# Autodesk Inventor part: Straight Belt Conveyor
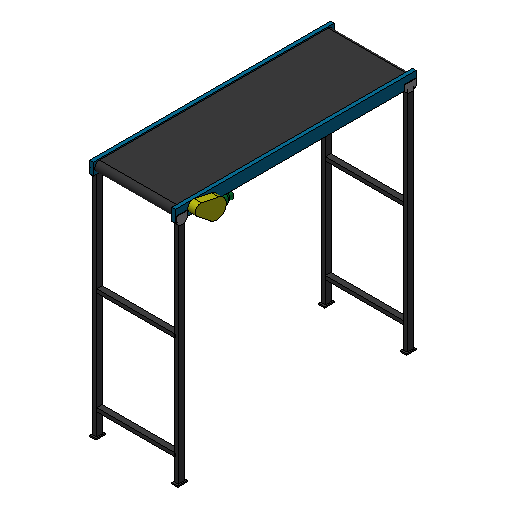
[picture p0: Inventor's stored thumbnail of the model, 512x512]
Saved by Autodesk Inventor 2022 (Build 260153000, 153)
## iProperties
ConnectorClass: Conveyor
family_type: normal
Created: 2009-10
Part Number: Straight Belt Conveyor
Document SubType Name: Modeling
Density: 1 g/cm^3
Material: 一般
Appearance: 既定
Key Parameters: Height=2000.000 mm;Width=710.000 mm;Length=2000.000 mm;RollerDiameter=80.000 mm;NumberOfRungs=2.000 ul;FeetGap=1000.000 mm;MotorLocation="Front-Right";Legs="All
Title: Straight Belt Conveyor
Author: Autodesk, Inc.
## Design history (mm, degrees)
sketch "Sketch1"
  geometry: L1 (1900, 1000)-(1900, -1000); L2 (1900, -1000)-(2000, -1000); L3 (2000, -1000)-(2000, 1000); L4 (2000, 1000)-(1900, 1000); L5 (1950, 1000)-(0, 1000); L6 (1950, -1000)-(0, -1000); L7 (0, -1000)-(0, 1000); L8 (0, -1400)-(0, 1400) reference; 2 further points
  constraints: 14 end point, 3 midpoint, 3 perpendicular, 2 coincident, 2 parallel, 1 collinear
  dimensions: "d110" = 100 distance between parallel lines of L1 L3 (= RailHeight); "d292" = 2000 distance of L6.end L5.end (derived); "d408" = 2000 distance from line of L8 L3.end (derived); "d409" = 2000 distance from line of L7 L2.end (derived)
extrude "Rail1" new body sketch "Sketch1" distance "d112" = 30 (= RailThickness); taper "d113" = 0 deg
node "MID"
mirror "Rail2"
sketch "Sketch8"
  geometry: L1 (-0.5, -25)-(-29.5, -25); L2 (-29.5, -25)-(-29.5, -75); L3 (-29.5, -75)-(-0.5, -75); L4 (-0.5, -75)-(-0.5, -25); L5 (-680, 0)-(-710, 0); L6 (-680.5, -25)-(-709.5, -25); L7 (-709.5, -25)-(-709.5, -75); L8 (-709.5, -75)-(-680.5, -75); L9 (-680.5, -75)-(-680.5, -25); L10 (-30, 0)-(0, 0); 4 further points
  constraints: 20 end point, 4 midpoint, 4 parallel, 3 perpendicular, 2 equal length, 2 horizontal, 2 vertical alignment
  dimensions: "d805" = 29 distance between parallel lines of L2 L4 (derived); "d806" = 50 distance between parallel lines of L3 L1; "d809" = 29 distance between parallel lines of L7 L9; "d810" = 50 distance between parallel lines of L6 L8 (derived); "d811" = 25 distance between parallel lines of L6 L5; "d812" = 25 distance between parallel lines of L1 L10 (derived)
extrude "Leg Mid 1" join sketch "Sketch8" distance "d731" = 1900 (derived); taper "d732" = 0 deg
sketch "Sketch9"
  geometry: L1 (2.5, -1680)-(47.5, -1680); L2 (47.5, -1680)-(47.5, -1710); L3 (47.5, -1710)-(2.5, -1710); L4 (2.5, -1710)-(2.5, -1680); L5 (50, -1900)-(0, -1900) reference; 2 further points
  constraints: 8 end point, 2 midpoint, 2 parallel, 1 horizontal, 1 perpendicular, 1 vertical alignment
  dimensions: "d1060" = 30 distance of L3.end L1.start; "d1071" = 190 distance between parallel lines of L3 L5 (derived); "d1072" = 45 distance of L1.start L1.end
extrude "Rung Mid 1" join sketch "Sketch9" stored distance "d739" = 650 (derived); taper "d740" = 0 deg
node "ToCutBelow"
sketch "ToBeenCutOne"
  geometry: L1 (-30, 1000)-(-680, 1000); L2 (-355, 1000)-(-355, 400); L3 (-30, -1000)-(-680, -1000); L4 (-355, -1000)-(-355, 400); L5 (-284, 400)-(-426, 400); C1 r 35.5 at (-284, 400); C2 r 35.5 at (-426, 400); 1 further point
  constraints: 10 end point, 4 coincident, 4 perpendicular, 3 midpoint, 2 centre point, 1 horizontal
  dimensions: "d720" = 600 distance of L2.start L2.end (derived); "d756" = 142 distance of L5.start L5.end (derived); "d813" = 71 diameter of C1 (derived); "d814" = 71 diameter of C2 (derived)
extrude "ToBeenCutMid" join sketch "ToBeenCutOne" distance "d817" = 25 (derived); taper "d818" = 0 deg
sketch "Sketch10"
  geometry: L1 (-680, 100)-(-30, 100); L2 (-30, 100)-(-30, 0); L3 (-30, 0)-(-680, 0); L4 (-680, 0)-(-680, 100)
  constraints: 8 end point, 2 parallel, 1 horizontal, 1 perpendicular
extrude "Cut Mid" cut sketch "Sketch10" distance "d744" = 2000 (derived); taper "d745" = 0 deg
pattern_linear "Rung Mid 2" dims "d743" = 855 (derived)
sketch "Sketch11"
  geometry: L1 (-0.5, -25)-(-0.5, -75) reference; L2 (-29.5, -25)-(-0.5, -25) reference; L3 (-29.5, -75)-(-29.5, -25) reference; L4 (-0.5, -75)-(-29.5, -75) reference; L5 (-680.5, -25)-(-680.5, -75) reference; L6 (-709.5, -25)-(-680.5, -25) reference; L7 (-709.5, -75)-(-709.5, -25) reference; L8 (-680.5, -75)-(-709.5, -75) reference; L9 (10, -10)-(-40, -10); L10 (-40, -10)-(-40, -90); L11 (-40, -90)-(10, -90); L12 (10, -90)-(10, -10); L13 (-670, -10)-(-720, -10); L14 (-720, -10)-(-720, -90); L15 (-720, -90)-(-670, -90); L16 (-670, -90)-(-670, -10); 9 further points
  constraints: 16 end point, 8 midpoint, 4 parallel, 2 horizontal, 2 horizontal alignment, 2 perpendicular, 2 vertical alignment
  dimensions: "d1001" = 80 distance of L11.end L9.start; "d1002" = 50 distance of L10.end L11.end; "d1003" = 80 distance of L15.end L13.start; "d1004" = 50 distance of L14.end L15.end
extrude "LegBase" join sketch "Sketch11" distance "d1005" = 10.2 (derived); taper "d1006" = 0 deg
sketch "Sketch12"
  geometry: L1 (50, 0)-(0, 0) reference; L2 (-24, 47.55)-(74, 47.55); L3 (74, 47.55)-(74, -2.45); L4 (74, -2.45)-(45, -30); L5 (45, -30)-(5, -30); L6 (5, -30)-(-24, -2.45); L7 (-24, -2.45)-(-24, 47.55); L8 (0, -1889.8)-(50, -1889.8) reference; L9 (0, 0)-(50, 0) reference; 7 further points
  constraints: 12 end point, 5 midpoint, 4 vertical alignment, 3 equal length, 2 parallel, 2 perpendicular
  dimensions: "d1007" = 40 distance of L4.end L5.end; "d1008" = 98 distance of L2.start L2.end; "d1009" = 30 distance between parallel lines of L1 L5; "d1011" = 50 distance of L6.end L2.start
extrude "LegPan" join sketch "Sketch12" distance "d1012" = 5.1 (derived); taper "d1013" = 0 deg
mirror "LegPanE"
pattern_linear "Leg Mid 2"
pattern_linear "Leg Mid 3" dims "d1075" = 1900 (derived)
mirror "LegMid3"
mirror "LegMid4"
sketch "Sketch20"
  geometry: L1 (-950, 1990)-(950, 1990); L2 (-950, 1910)-(950, 1910); L3 (950, 1990)-(950, 1910); L4 (-950, 1910)-(-950, 1990); L5 (-950, 1950)-(-950, 1950); L6 (-1000, 1900)-(-1000, 2000) reference; L7 (1000, 2000)-(1000, 1900) reference; L8 (-950, 1950)-(-1000, 1950); L9 (950, 1950)-(1000, 1950); L10 (-1000, 2000)-(-1000, 1900) reference; L11 (1000, 1900)-(1000, 2000) reference; C1 r 40 at (-950, 1950); A1 r 40 centre (950, 1950) between (950, 1990) and (950, 1910)
  constraints: 14 end point, 4 midpoint, 4 tangent, 2 centre point, 2 equal length, 2 horizontal alignment, 2 point on circle
  dimensions: "d820" = 80 diameter of A1 (derived); "d831" = 80 diameter of C1 (derived); "d1000" = 0 distance of L5.start L5.end; "d1014" = 50 distance of L5.start L8.end (derived); "d1015" = 50 distance of L9.start L9.end (derived)
extrude "BeltMid" join sketch "Sketch20" distance "d821" = 650 (derived); taper "d822" = 0 deg
sketch "Sketch29"
  geometry: L1 (-1000, 1900)-(-1000, 2000) reference; L2 (1000, 2000)-(1000, 1900) reference; L3 (1000, 1900)-(-1000, 1900) reference; L4 (-1000, 2000)-(1000, 2000) reference; L5 (0, 2000)-(0, 1899); L6 (-75, 1899)-(75, 1899); L7 (-75, 1999)-(75, 1999); L8 (-75, 1799)-(75, 1799); A1 r 100 centre (-75, 1899) between (-75, 1999) and (-75, 1799); A2 r 100 centre (75, 1899) between (75, 1799) and (75, 1999)
  constraints: 8 end point, 4 point on circle, 4 tangent, 2 centre point, 2 coincident, 2 midpoint, 2 parallel, 1 perpendicular
  dimensions: "d1067" = 101 distance of L5.start L5.end; "d1068" = 150 distance of L6.start L6.end; "d1069" = 100 radius of A1
extrude "M2.1" join sketch "Sketch29" distance "d898" = 50; taper "d899" = 0 deg
sketch "Sketch30"
  geometry: L1 (-174.995, 660)-(174.995, 660); L2 (0, 650)-(80, 650); L3 (80, 650)-(80, 550); L4 (80, 550)-(0, 550); L5 (0, 550)-(0, 650); 2 further points
  constraints: 10 end point, 2 midpoint, 2 perpendicular, 1 horizontal, 1 parallel, 1 vertical alignment
  dimensions: "d900" = 100 distance of L4.end L2.start; "d901" = 80 distance of L3.end L4.end; "d1070" = 10 distance between parallel lines of L1 L2
extrude "M2.2" join sketch "Sketch30" distance "d902" = 100; taper "d903" = 0 deg
sketch "Sketch31"
  geometry: L1 (-100, 100)-(-100, 0) reference; L2 (0, 0)-(-100, 0) reference; L3 (0, 100)-(0, 9.125) reference; C1 r 50 at (-50, 50); 2 further points
  constraints: 3 tangent, 1 centre point
extrude "M2.3" join sketch "Sketch31" distance "d904" = 80; taper "d905" = 0 deg
sketch "Sketch32" dims "d907" = 100 (derived)
  geometry: C1 r 15 at (0, 0); 3 further points
  constraints: 1 centre point, 1 coincident, 1 horizontal alignment
  dimensions: "d906" = 30 diameter of C1
extrude "M2.4" join sketch "Sketch32" distance "d908" = 20; taper "d909" = 0 deg
sketch "Sketch33"
  geometry: C1 r 15 at (0, 0) reference; C2 r 40 at (0, 0); 1 further point
  constraints: 1 centre point, 1 coincident
  dimensions: "d910" = 80 diameter of C2
extrude "M2.5" join sketch "Sketch33" distance "d911" = 30; taper "d912" = 0 deg
sketch "Sketch34"
  geometry: L1 (1000, 2000)-(1000, 1900); L2 (1000, 2000)-(1000, 1900) reference; L3 (843.023, 1999.096)-(700.095, 1969.999); L4 (765.848, 1828.993)-(880.009, 1919.779); L5 (-1000, 1900)-(1000, 1900) reference; L6 (852, 1955)-(716.054, 1891.607); L7 (-1000, 2000)-(1000, 2000) reference; A1 r 45 centre (852, 1955) between (880.009, 1919.779) and (843.023, 1999.096); A2 r 80 centre (716.054, 1891.607) between (700.095, 1969.999) and (765.848, 1828.993)
  constraints: 8 end point, 5 tangent, 4 point on circle, 2 centre point, 1 vertical
  dimensions: "d913" = 90 diameter of A1; "d1078" = 150 distance of L6.start L6.end; "d1079" = 148 distance from line of L1 L6.start; "d1080" = 80 radius of A2; "d1081" = 25 deg angle of L5 L6
extrude "M1.1" join sketch "Sketch34" distance "d915" = 50; taper "d916" = 0 deg
sketch "Sketch35"
  geometry: L1 (-716.054, 651.607)-(-636.054, 651.607); L2 (-636.054, 651.607)-(-636.054, 551.607); L3 (-636.054, 551.607)-(-716.054, 551.607); L4 (-716.054, 551.607)-(-716.054, 651.607); A1 r 80 centre (-716.054, 651.607) between (-636.495, 660) and (-765.848, 588.993) reference; 1 further point
  constraints: 8 end point, 2 parallel, 1 horizontal, 1 perpendicular
  dimensions: "d917" = 100 distance of L3.end L1.start; "d1077" = 80 distance of L2.end L3.end
extrude "M1.2" join sketch "Sketch35" distance "d918" = 98; taper "d919" = 0 deg
sketch "Sketch36"
  geometry: L1 (-98, 100)-(-98, 0) reference; L2 (0, 0)-(-98, 0) reference; L3 (0, 0)-(0, 100) reference; C1 r 49 at (-49, 49); 1 further point
  constraints: 3 tangent, 1 centre point
extrude "M1.3" join sketch "Sketch36" distance "d920" = 80; taper "d921" = 0 deg
sketch "Sketch37"
  geometry: C1 r 49 at (0, 0) reference; C2 r 15 at (0, 0); 1 further point
  constraints: 1 centre point, 1 coincident
  dimensions: "d922" = 98 diameter of C1 (derived); "d923" = 30 diameter of C2
extrude "M1.4" join sketch "Sketch37" distance "d924" = 20; taper "d925" = 0 deg
sketch "Sketch38"
  geometry: C1 r 15 at (0, 0) reference; C2 r 40 at (0, 0); 1 further point
  constraints: 1 centre point, 1 coincident
  dimensions: "d926" = 80 diameter of C2
extrude "M1.5" join sketch "Sketch38" distance "d927" = 30; taper "d928" = 0 deg
sketch "Sketch39"
  geometry: L1 (-1000, 1900)-(-1000, 2000) reference; L2 (-843.023, 1999.096)-(-700.095, 1969.999); L3 (-880.009, 1919.779)-(-765.848, 1828.993); L4 (1000, 2000)-(-1000, 2000) reference; L5 (-1000, 1900)-(1000, 1900) reference; L6 (-852, 1955)-(-716.054, 1891.607); L7 (901, 1900)-(999, 1900) reference; A1 r 45 centre (-852, 1955) between (-843.023, 1999.096) and (-880.009, 1919.779); A2 r 80 centre (-716.054, 1891.607) between (-765.848, 1828.993) and (-700.095, 1969.999); A3 r 45 centre (-852, 1955) between (-843.023, 1999.096) and (-880.009, 1919.779); 1 further point
  constraints: 6 end point, 6 point on circle, 4 tangent, 3 centre point, 1 coincident, 1 concentric
  dimensions: "d929" = 90 diameter of A1; "d932" = 160 diameter of A2; "d1082" = 148 distance from line of A1.centre L1; "d1083" = 150 distance of L6.start L6.end; "d1084" = 25 deg angle of L5 L6; "d1111" = 55 distance from line of L7 A1.centre
extrude "M3.1" join sketch "Sketch39" distance "d933" = 60 (derived); taper "d934" = 0 deg
sketch "Sketch40"
  geometry: L1 (716.054, 653.607)-(636.054, 653.607); L2 (636.054, 653.607)-(636.054, 553.607); L3 (636.054, 553.607)-(716.054, 553.607); L4 (716.054, 553.607)-(716.054, 653.607); 4 further points
  constraints: 8 end point, 2 parallel, 1 coincident, 1 horizontal, 1 perpendicular, 1 other
  dimensions: "d935" = 80 distance of L2.end L3.end; "d1085" = 100 distance of L1.end L2.end
extrude "M3.2" join sketch "Sketch40" distance "d936" = 98; taper "d937" = 0 deg
sketch "Sketch41"
  geometry: L1 (98, 0)-(98, 100) reference; L2 (0, 100)-(0, 0) reference; L3 (0, 0)-(98, 0) reference; C1 r 49 at (49, 49); 4 further points
  constraints: 3 tangent, 1 centre point
extrude "M3.3" join sketch "Sketch41" distance "d938" = 80; taper "d939" = 0 deg
sketch "Sketch42"
  geometry: C1 r 49 at (0, 0) reference; C2 r 15 at (0, 0); 1 further point
  constraints: 1 centre point, 1 coincident
  dimensions: "d940" = 30 diameter of C2; "d941" = 98 diameter of C1 (derived)
extrude "M3.4" join sketch "Sketch42" distance "d942" = 20; taper "d943" = 0 deg
sketch "Sketch43"
  geometry: C1 r 15 at (0, 0) reference; C2 r 40 at (0, 0); 1 further point
  constraints: 1 centre point, 1 coincident
  dimensions: "d944" = 80 diameter of C2
extrude "M3.5" join sketch "Sketch43" distance "d945" = 30; taper "d946" = 0 deg
sketch "Sketch44"
  geometry: L1 (-2000, 100)-(-2000, 0) reference; L2 (-1843.023, 99.096)-(-1700.095, 69.999); L3 (-1765.848, -71.007)-(-1880.009, 19.779); L4 (-1852, 55)-(-1716.054, -8.393); L5 (0, 0)-(-2000, 0) reference; L6 (-2000, 100)-(0, 100) reference; A1 r 45 centre (-1852, 55) between (-1843.023, 99.096) and (-1880.009, 19.779); A2 r 80 centre (-1716.054, -8.393) between (-1765.848, -71.007) and (-1700.095, 69.999); A3 r 45 centre (-1852, 55) between (-1843.023, 99.096) and (-1880.009, 19.779)
  constraints: 6 end point, 6 point on circle, 5 tangent, 3 centre point, 1 coincident
  dimensions: "d948" = 90 diameter of A1; "d949" = 160 diameter of A2; "d1086" = 150 distance of L4.start L4.end; "d1087" = 25 deg angle of L4 L5; "d1088" = 148 distance from line of A1.centre L1
extrude "M4.1" join sketch "Sketch44" distance "d950" = 60 (derived); taper "d951" = 0 deg
sketch "Sketch45"
  geometry: L1 (1716.054, -8.393)-(1636.054, -8.393); L2 (1636.054, -8.393)-(1636.054, -108.393); L3 (1636.054, -108.393)-(1716.054, -108.393); L4 (1716.054, -108.393)-(1716.054, -8.393); A1 r 80 centre (1716.054, -8.393) between (1636.495, 0) and (1765.848, -71.007) reference
  constraints: 8 end point, 2 parallel, 1 coincident, 1 horizontal, 1 perpendicular
  dimensions: "d952" = 100 distance of L3.end L1.start; "d1089" = 80 distance of L2.end L3.end
extrude "M4.2" join sketch "Sketch45" distance "d953" = 100; taper "d954" = 0 deg
sketch "Sketch46"
  geometry: L1 (100, 0)-(100, 100) reference; L2 (0, 100)-(0, 0) reference; L3 (0, 0)-(100, 0) reference; C1 r 50 at (50, 50); 3 further points
  constraints: 3 tangent, 1 centre point
extrude "M4.3" join sketch "Sketch46" distance "d955" = 80; taper "d956" = 0 deg
sketch "Sketch47"
  geometry: C1 r 50 at (0, 0) reference; C2 r 15 at (0, 0); 1 further point
  constraints: 1 centre point, 1 coincident
  dimensions: "d957" = 100 diameter of C1 (derived); "d958" = 30 diameter of C2
extrude "M4.4" join sketch "Sketch47" distance "d959" = 20; taper "d960" = 0 deg
sketch "Sketch48"
  geometry: C1 r 15 at (0, 0) reference; C2 r 40 at (0, 0); 1 further point
  constraints: 1 centre point, 1 coincident
  dimensions: "d961" = 80 diameter of C2
extrude "M4.5" join sketch "Sketch48" distance "d962" = 30; taper "d963" = 0 deg
sketch "Sketch49"
  geometry: L1 (-1075, 99)-(-925, 99); L2 (-925, -101)-(-1075, -101); L3 (-2000, 100)-(0, 100) reference; L4 (-1000, 100)-(-1000, -1); L5 (-1075, -1)-(-925, -1); A1 r 100 centre (-1075, -1) between (-1075, 99) and (-1075, -101); A2 r 100 centre (-925, -1) between (-925, -101) and (-925, 99)
  constraints: 8 end point, 4 point on circle, 4 tangent, 2 centre point, 2 coincident, 2 midpoint, 2 perpendicular, 1 equal radius, 1 parallel
  dimensions: "d964" = 200 diameter of A1; "d1090" = 101 distance of L4.start L4.end; "d1091" = 150 distance of L5.start L5.end
extrude "M5.1" join sketch "Sketch49" distance "d965" = 50; taper "d966" = 0 deg
sketch "Sketch50"
  geometry: L1 (920, -10)-(1000, -10); L2 (1000, -10)-(1000, -110); L3 (1000, -110)-(920, -110); L4 (920, -110)-(920, -10); L5 (1174.995, 0)-(825.005, 0) reference; 2 further points
  constraints: 8 end point, 2 midpoint, 2 parallel, 1 horizontal, 1 perpendicular, 1 vertical alignment
  dimensions: "d967" = 100 distance of L3.end L1.start; "d968" = 80 distance between parallel lines of L2 L4; "d1092" = 10 distance between parallel lines of L1 L5
extrude "M5.2" join sketch "Sketch50" distance "d969" = 98; taper "d970" = 0 deg
sketch "Sketch51"
  geometry: L1 (98, -9)-(98, 91) reference; L2 (0, -9)-(98, -9) reference; C1 r 49 at (49, 40); 2 further points
  constraints: 2 tangent, 1 centre point, 1 vertical alignment, 1 other
extrude "M5.3" join sketch "Sketch51" distance "d971" = 80; taper "d972" = 0 deg
sketch "Sketch52" dims "d974" = 98 (derived)
  geometry: C1 r 15 at (0, 0); 3 further points
  constraints: 1 centre point, 1 coincident, 1 horizontal alignment
  dimensions: "d973" = 30 diameter of C1
extrude "M5.4" join sketch "Sketch52" distance "d975" = 20; taper "d976" = 0 deg
sketch "Sketch53"
  geometry: C1 r 15 at (0, 0) reference; C2 r 40 at (0, 0); 1 further point
  constraints: 1 centre point, 1 coincident
  dimensions: "d977" = 80 diameter of C2
extrude "M5.5" join sketch "Sketch53" distance "d978" = 30; taper "d979" = 0 deg
sketch "Sketch54"
  geometry: L1 (0, 0)-(0, 100) reference; L2 (-156.977, 99.096)-(-299.905, 69.999); L3 (-119.991, 19.779)-(-234.152, -71.007); L4 (0, 0)-(-2000, 0) reference; L5 (-283.946, -8.393)-(-148, 55); A1 r 45 centre (-148, 55) between (-119.991, 19.779) and (-156.977, 99.096); A2 r 80 centre (-283.946, -8.393) between (-299.905, 69.999) and (-234.152, -71.007)
  constraints: 6 end point, 4 point on circle, 4 tangent, 2 centre point
  dimensions: "d981" = 90 diameter of A1; "d984" = 160 diameter of A2; "d1093" = 150 distance of L5.start L5.end; "d1094" = 25 deg angle of L4 L5; "d1095" = 148 distance from line of L5.end L1; "d1112" = 55 distance from line of L4 L5.end
extrude "M6.1" join sketch "Sketch54" distance "d982" = 50; taper "d983" = 0 deg
sketch "Sketch55"
  geometry: L1 (283.946, -8.393)-(363.946, -8.393); L2 (363.946, -8.393)-(363.946, -108.393); L3 (363.946, -108.393)-(283.946, -108.393); L4 (283.946, -108.393)-(283.946, -8.393); 3 further points
  constraints: 8 end point, 2 parallel, 1 coincident, 1 horizontal, 1 perpendicular, 1 other
  dimensions: "d985" = 100 distance of L3.end L1.start; "d986" = 80 distance of L2.end L3.end
extrude "M6.2" join sketch "Sketch55" distance "d987" = 98; taper "d988" = 0 deg
sketch "Sketch56"
  geometry: L1 (-98, 100)-(-98, 0) reference; L2 (0, 0)-(-98, 0) reference; L3 (0, 0)-(0, 100) reference; C1 r 49 at (-49, 49); 3 further points
  constraints: 3 tangent, 1 centre point
extrude "M6.3" join sketch "Sketch56" distance "d989" = 80; taper "d990" = 0 deg
sketch "Sketch57"
  geometry: C1 r 49 at (0, 0) reference; C2 r 15 at (0, 0); 1 further point
  constraints: 1 centre point, 1 coincident
  dimensions: "d991" = 30 diameter of C2
extrude "M6.4" join sketch "Sketch57" distance "d992" = 20; taper "d993" = 0 deg
sketch "Sketch58"
  geometry: C1 r 15 at (0, 0) reference; C2 r 40 at (0, 0); 1 further point
  constraints: 1 centre point, 1 coincident
  dimensions: "d994" = 80 diameter of C2
extrude "M6.5" join sketch "Sketch58" distance "d995" = 30; taper "d996" = 0 deg
node "Landing Surface_Work Plane1"
node "Landing Surface_Work Plane2"
workpoint "Work Point1"
  workplane "Work Plane22"
  workplane "Work Plane23"
node "Connector_Work Axis1"
node "Connector 1_Work Point1"
node "Connector 2_Work Point1"
node "Connector1"
node "Connector2"
workplane "Work Plane28"
node "Landing Surface"
node "Insertion Point1"
body "Solid5"
node "Projected Loop14"
node "Projected Loop15"
node "Projected Loop17"
node "Projected Loop18"
other parameters: "RailThickness" = 30 [user parameter; used in 1 equation term], "RailHeight" = 100 [user parameter; used in 1 equation term], "Thickness" = 10.2 [user parameter], "d162" = 355 (derived), "Location_" = 3 [user parameter], "Angle" = 45 deg [user parameter], "BranchLength" = 991 [user parameter], "RungDistance" = 855 [user parameter], "Location" = 3 [user parameter], "Length2_q" = 991 [user parameter], "Angle_q" = 45 deg [user parameter], "d1113" = 355, "d1116" = 90 deg, "d1117" = 0, "d1118" = 90 deg, "d1119" = 355, "d1122" = 90 deg, "d1123" = 0, "d1124" = -90 deg
